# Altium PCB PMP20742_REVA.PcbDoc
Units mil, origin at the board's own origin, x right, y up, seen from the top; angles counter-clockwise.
Board outline 3000 x 1500 mil, 2 copper layers (Top Layer, Bottom Layer), stack 62 mil thick; 73 components, 37 nets, 234 pads, 52 vias.
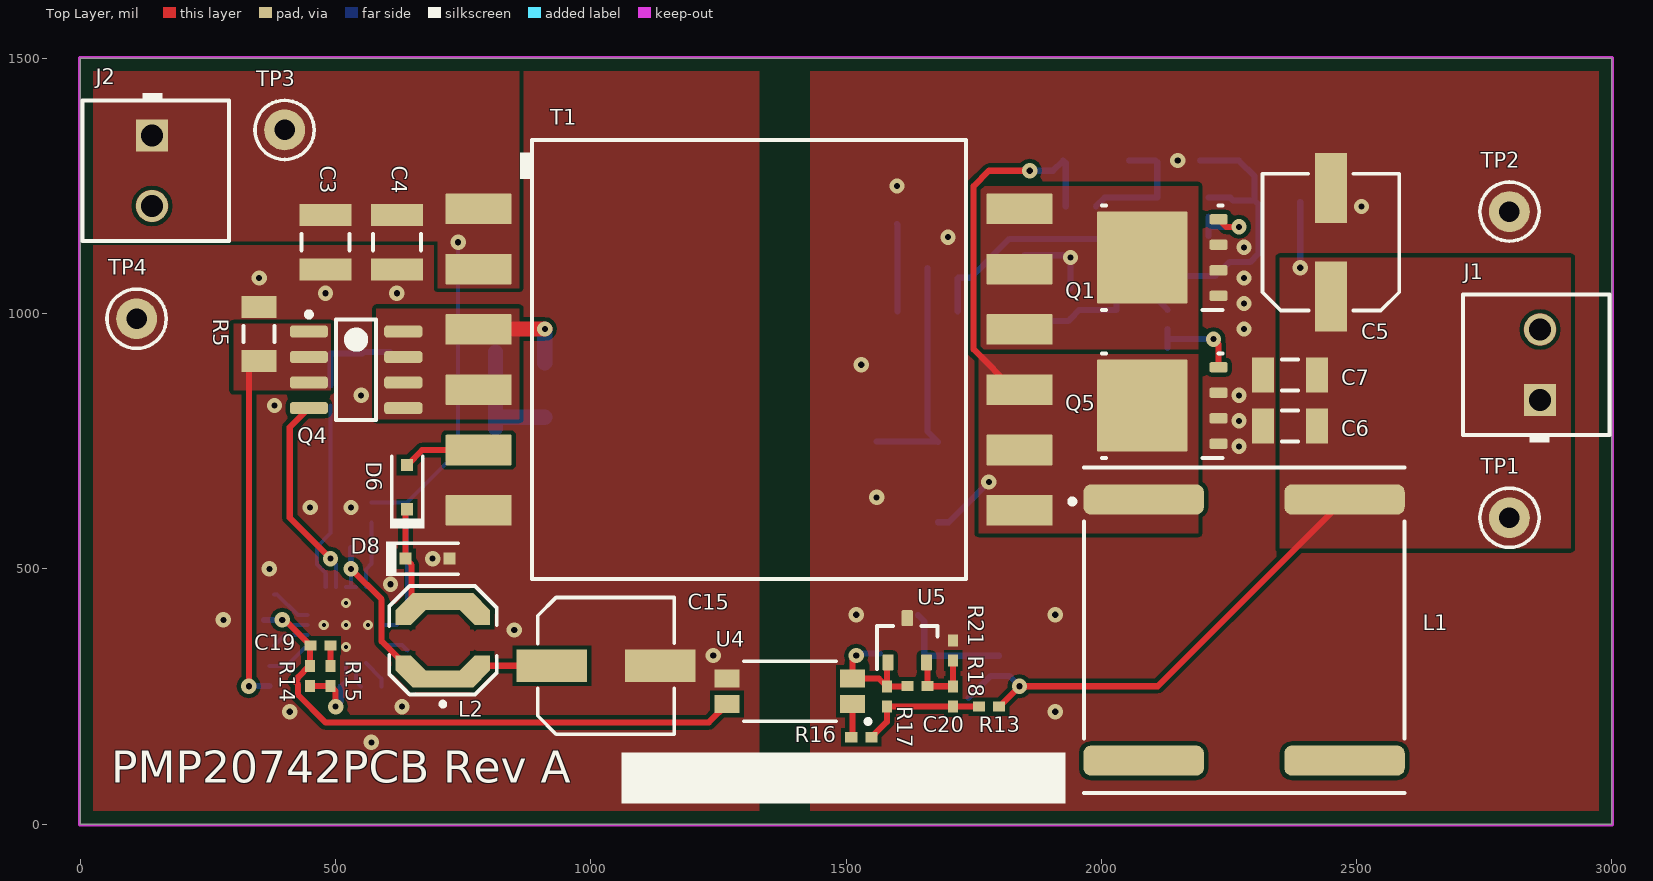
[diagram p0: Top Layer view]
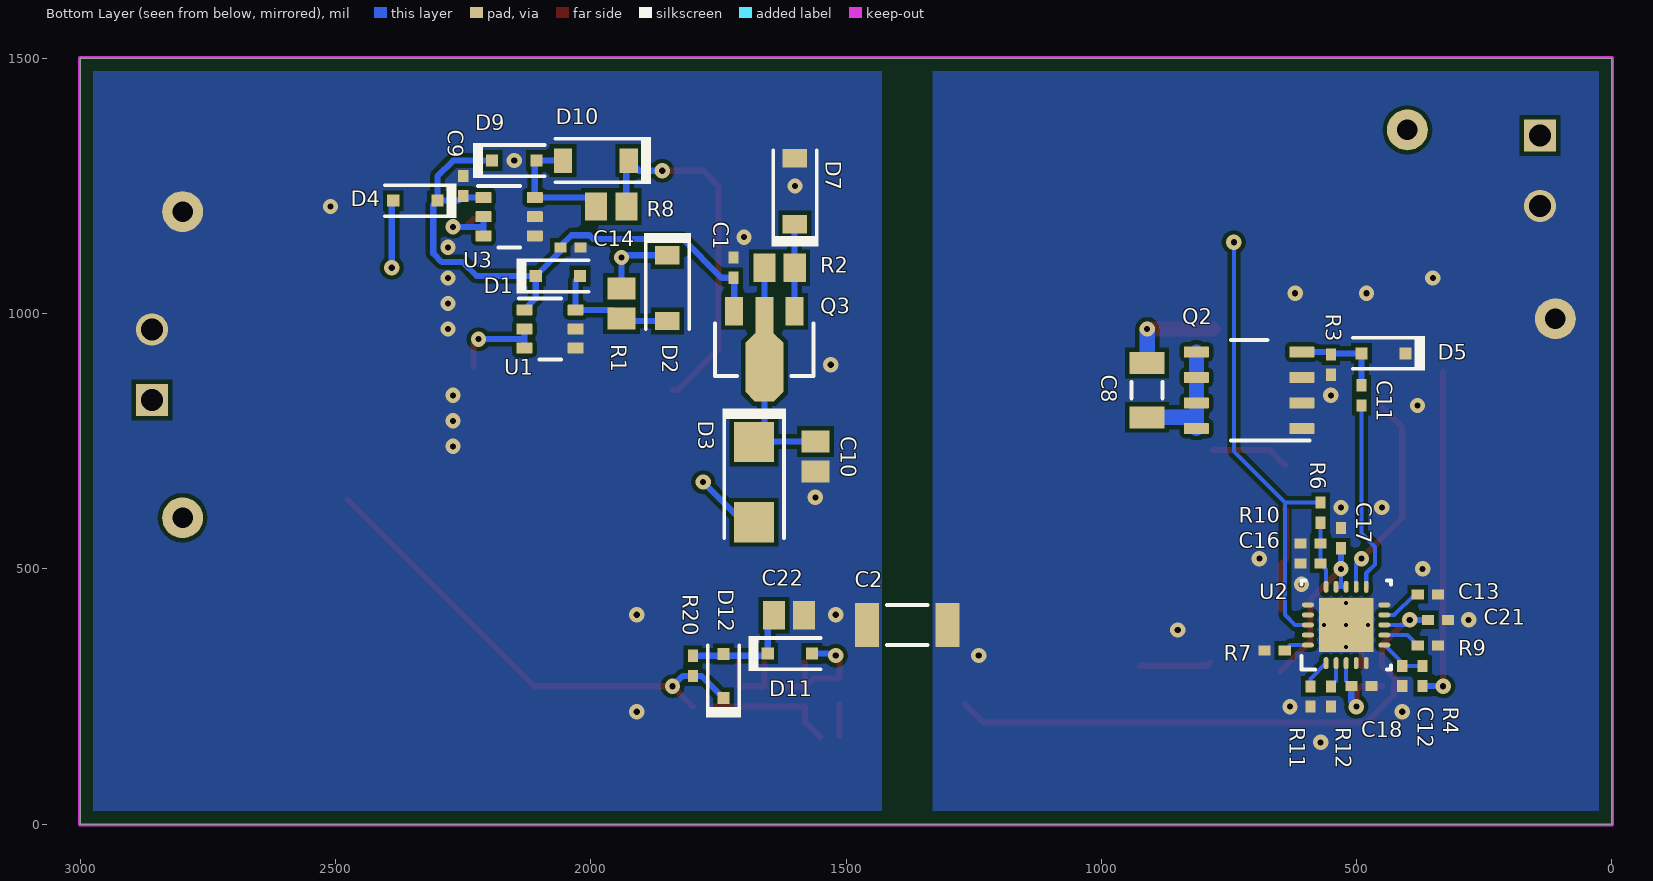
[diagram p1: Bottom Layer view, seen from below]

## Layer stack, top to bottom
Top Solder: solder mask 0.4, Solder Resist, Dk 3.5
Top Layer: signal copper 1.4
Dielectric1: core 59.2, FR-4, Dk 4.8
Bottom Layer: signal copper 1.4
Bottom Solder: solder mask 0.4, Solder Resist, Dk 3.5

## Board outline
0,0 3000,0 3000,1500 0,1500

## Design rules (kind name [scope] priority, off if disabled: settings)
AcuteAngle [All] p1: minimum=0.00000000000000E+0000 checktracksonly=FALSE
AssemblyTestPointUsage [All] p1: valid=2
BoardOutlineClearance BoardOutlineClearance_MountingHoles [OnCopper and InComponentClass('Mounting Holes')] p1: gap=25
BoardOutlineClearance BoardOutlineClearance_Poly [OnCopper and InPoly] p2: gap=25
BoardOutlineClearance [OnCopper and Not InComponentClass('Logo') and not InComponentClass('FiducialMark') and not InRegion(1000,500,4000,800)] p3: gap=25
Clearance Clearance_Keepouts [((IsTrack Or IsArc) And Not InPoly) And IsFree and IsKeepOut vs ((IsTrack Or IsArc) And Not InPoly) And IsFree and IsKeepOut] p1: gap=0
Clearance Clearance_Poly [InPolygon] p2: gap=8
Clearance [All] p3: gap=7.87
ComponentClearance ComponentClearance_MountingHoles_FiducialMarks [InComponentClass('Mounting Holes') vs InComponentClass('FiducialMark')] p1: gap=50 collisioncheckmode=3 verticalgap=10 showdistances=FALSE
ComponentClearance ComponentClearance_Shunt [InComponentClass('Header') vs InComponentClass('Shunt')] p2: gap=0 collisioncheckmode=3 verticalgap=0 showdistances=FALSE
ComponentClearance ComponentClearance_Logo [InComponentClass('Logo')] p3: gap=50 collisioncheckmode=3 verticalgap=10 showdistances=FALSE
ComponentClearance ComponentClearance_ScrewToNut [(HasFootprint('NY PMS 440 0025 PH')) vs (HasFootprint('Keystone_1902C'))] p4: gap=5 collisioncheckmode=3 verticalgap=10 showdistances=FALSE
ComponentClearance ComponentClearance_MountingHoles [InComponentClass('Mounting Holes')] p5: gap=250 collisioncheckmode=3 verticalgap=100000 showdistances=FALSE
ComponentClearance ComponentClearance_SmallPassives [HasFootprint('0201*') or HasFootprint('0402*') or HasFootprint('0508') or HasFootprint('0603*') or HasFootprint('0612') or HasFootprint('0805*') or HasFootprint('0815*') or HasFootprint('0830*') or HasFootprint('1206*') or HasFootprint('1210*') or HasFootprint('1808*') or HasFootprint('1812*') or HasFootprint('1825*') or HasFootprint('2010*') or HasFootprint('2220*') or HasFootprint('2225*') or HasFootprint('2512*') or HasFootprint('2728*') or HasFootprint('3518*') vs HasFootprint('0201*') or HasFootprint('0402*') or HasFootprint('0508') or HasFootprint('0603*') or HasFootprint('0612') or HasFootprint('0805*') or HasFootprint('0815*') or HasFootprint('0830*') or HasFootprint('1206*') or HasFootprint('1210*') or HasFootprint('1808*') or HasFootprint('1812*') or HasFootprint('1825*') or HasFootprint('2010*') or HasFootprint('2220*') or HasFootprint('2225*') or HasFootprint('2512*') or HasFootprint('2728*') or HasFootprint('3518*')] p6: gap=14.96 collisioncheckmode=3 verticalgap=10 showdistances=FALSE
ComponentClearance ComponentClearance_THtoSMT [IsThruComponent vs IsSMTComponent] p7: gap=15 collisioncheckmode=3 verticalgap=30 showdistances=FALSE
ComponentClearance ComponentClearance_THtoTH [IsThruComponent vs IsThruComponent] p8: gap=15 collisioncheckmode=3 verticalgap=30 showdistances=FALSE
ComponentClearance [All] p9: gap=15 collisioncheckmode=3 verticalgap=10 showdistances=FALSE
DiffPairsRouting [All] p1: maxlimit=100 minlimit=10 mostfreqgap=10 toplayer_minwidth=15 toplayer_maxwidth=15 toplayer_prefwidth=15 bottomlayer_minwidth=15 bottomlayer_maxwidth=15 bottomlayer_prefwidth=15 maxuncoupledlength=1000
FabricationTestPointUsage TestPointUsage [All] p1: valid=2 allowmultiple=FALSE
FabricationTestpoint Testpoint [All] p1: side=3 testpointundercomponent=TRUE minsize=40 maxsize=100 preferedsize=60 minholesize=0 maxholesize=40 preferedholesize=32 testpointgrid=1 allowsidetop=TRUE allowsidebottom=TRUE usegrid=TRUE gridtolerance=0.01
FanoutControl Fanout_LCC [IsLCC] p1: bgadir=Out bgaviamode=Centered fanoutstyle=Auto fanoutdirection=Alternating viagrid=1 // Fanout_LCC (Default Rule)
FanoutControl Fanout_BGA [IsBGA] p2: bgadir=Out bgaviamode=Centered fanoutstyle=Auto fanoutdirection=Alternating viagrid=1 // Fanout_BGA (Default Rule)
FanoutControl Fanout_Default [All] p4: bgadir=Out bgaviamode=Centered fanoutstyle=Auto fanoutdirection=Alternating viagrid=1 // Fanout_Default (Default Rule)
FanoutControl Fanout_Small [(CompPinCount < 5)] p5: bgadir=Out bgaviamode=Centered fanoutstyle=Auto fanoutdirection=OutThenIn viagrid=1 // Fanout_Small (Default Rule)
HoleSize [All] p1: absolutevalues=TRUE maxlimit=251 minlimit=7.87 maxpercent=80.000 minpercent=20.000
MinimumAnnularRing MinimumAnnularRing_ThermalPadVias [IsVia and InAnyComponent] p1: minimumring=5.91
MinimumAnnularRing [All] p2: minimumring=8
MinimumSolderMaskSliver MinimumSolderMaskSliver_Logo [InComponentClass('Logo') vs InComponentClass('Logo')] p1: minsoldermaskwidth=0.7
MinimumSolderMaskSliver [All] p2: minsoldermaskwidth=3.94
PlaneConnect [All] p1: planeconnectstyle=Direct reliefexpansion=10 reliefentries=4 reliefconductorwidth=10 reliefairgap=10
PolygonConnect [All] p1: connectstyle=Direct reliefconductorwidth=10 reliefentries=4 polygonreliefangle="90 Angle" airgapwidth=10
RoutingVias ThermalPadVias [IsVia and InAnyComponent] p1: holewidth=7.87 width=19.68 viastyle="Through Hole" minholewidth=7.87 minwidth=19.68 maxholewidth=12.99 maxwidth=23.62
RoutingVias [All] p2: holewidth=16 width=34 viastyle="Through Hole" minholewidth=7.87 minwidth=26 maxholewidth=40 maxwidth=65
SilkToBoardRegionClearance [Not ((IsComment or IsDesignator) And (Hide <> 'False')) and not InRegion(1000,500,4000,800)] p1:
SilkToSilkClearance SilkToSilkClearance_Pb-FreeLogo [(HasFootprint('Pb-Free_Overlay_Medium') OR HasFootprint('Pb-Free_Overlay_Small')) vs (HasFootprint('Pb-Free_Overlay_Medium') OR HasFootprint('Pb-Free_Overlay_Small'))] p1: silktosilkclearance=0
SilkToSilkClearance [All] p2: silktosilkclearance=4
SilkToSolderMaskClearance SilkToComponentPadClearance [IsPad and InAnycomponent] p1: minsilkscreentomaskgap=1 clearancetoexposedcopper=TRUE
SilkToSolderMaskClearance "Silk to Solder Mask Opening" [All] p2: minsilkscreentomaskgap=0.1 clearancetoexposedcopper=FALSE
SolderMaskExpansion [All] p1: expansion=1.97
Width [All] p1: maxlimit=100 minlimit=6 preferedwidth=10 checkconnectedcopper=TRUE
15 further rules are at their usual default settings.

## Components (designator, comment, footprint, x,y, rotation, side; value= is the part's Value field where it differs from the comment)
C1 "GRM155R71E104KE14D" 0402L 1720,1090 r90 bottom
C2 "STD" 1808_L 1380,390 r180 bottom
C3 "GRM32ER72A225KA35L" 1210_270L 480,1140 r270 top
C4 "GRM32ER72A225KA35L" 1210_270L 620,1140 r270 top
C5 "EEHZA1E101XP" SM_RADIAL_6.3BMM 2450,1140 r90 top
C6 "GRM31CC81E226ME11L" 1206_190L 2370,780 r180 top
C7 "GRM31CC81E226ME11L" 1206_190L 2370,880 r180 top
C8 "GRM31CR72E473KW03L" 1206_180L 910,850 r90 bottom
C9 "GRM155R71E104KE14D" 0402L 2250,1250 r90 bottom
C10 "GRM21BR72A473KA01L" 0805L 1560,720 r270 bottom
C11 "GRM155R71E104KE14D" 0402L 490,840 r90 bottom
C12 "GRM1555C1H221JA01D" 0402L 410,290 r90 bottom
C13 "GRM155R61A224KE19D" 0402L 360,450 r0 bottom
C14 "GRM155R71E104KE14D" 0402L 2040,1130 r180 bottom
C15 "EEHZA1E101XP" SM_RADIAL_6.3BMM 1030,310 r0 top
C16 "GRM155R71E473KA88D" 0402L 590,510 r180 bottom
C17 "GRM155R71E104KE14D" 0402L 530,560 r90 bottom
C18 "GRM155R61A105KE15D" 0402L 490,270 r180 bottom
C19 "GRM155R71E104KE14D" 0402L 470,350 r180 top
C20 "GRM155R71E103KA01D" 0402L 1640,270 r180 top
C21 "GRM155R61H102KA01D" 0402L 340,400 r180 bottom
C22 "GRM21BR71E475KA73L" 0805L 1611.75,409 r180 bottom
D1 "BAS316,115" sod-323 2064.57,1073.78 r180 bottom
D2 "BAV21W-7-F" SOD-123 1850,1050 r270 bottom
D3 "US1B-13-F" SMA 1680,670 r270 bottom
D4 "BAS316,115" sod-323 2343.82,1221.48 r0 bottom
D5 "BAS316,115" sod-323 446.57,922.28 r0 bottom
D6 "BAS316,115" sod-323 640,660 r90 top
D7 "MMSZ4692T1G" SOD-123 1600,1240 r90 bottom
D8 "BAS316,115" sod-323 680,520 r0 top
D9 "BAS316,115" sod-323 2150,1300 r180 bottom
D10 "BAV21W-7-F" SOD-123 1990,1300 r0 bottom
D11 "BAS316,115" sod-323 1610,334 r180 bottom
D12 "BAS316,115" sod-323 1740,290 r90 bottom
J1 "39357-0002" Molex_39357-0002 2860,900 r90 top
J2 "39357-0002" Molex_39357-0002 140,1280 r270 top
L1 "PD0120.113NL" PD0120NL 2280,380 r0 top
L2 "LPS4414-105MLB" LPS4414 710,360 r90 top
Q1 "CSD18537NQ5A" DQJ0008A 2120,1110 r180 top
Q2 "IRF6216TRPBF" SOIC-8L 710,850 r0 bottom
Q3 "BCX5616TA" SOT-89-3 1660,930 r270 bottom
Q4 "IRF7815TRPBF" SO-8L 540,890 r0 top
Q5 "CSD18537NQ5A" DQJ0008A 2120,820 r180 top
R1 "CRCW08055K10JNEA" 0805L 1940,1020 r270 bottom
R2 "CRCW080520K0FKEA" 0805L 1630,1090 r0 bottom
R3 "CRCW040210K0FKED" 0402L 550,900 r90 bottom
R4 "CRCW04021K00FKED" 0402L 370,290 r90 bottom
R5 "ERJ-8CWFR033V" 1206L 350,960 r270 top
R6 "CRCW040275K0FKED" 0402L 570,610 r90 bottom
R7 "CRCW040210K0FKED" 0402L 660,340 r180 bottom
R8 "CRCW08055K10JNEA" 0805L 1960,1210 r0 bottom
R9 "CRCW040249K9FKED" 0402L 360,350 r0 bottom
R10 "CRCW04022K80FKED" 0402L 590,550 r180 bottom
R11 "CRCW040280K6FKED" 0402L 590,250 r90 bottom
R12 "CRCW040263K4FKED" 0402L 550,250 r90 bottom
R13 "CRCW04020000Z0ED" 0402L 1780,230 r0 top
R14 "CRCW04021K00FKED" 0402L 450,290 r90 top
R15 "CRCW04021K00FKED" 0402L 490,290 r90 top
R16 "CRCW04022K00FKED" 0402L 1530,170 r0 top
R17 "CRCW04024K99FKED" 0402L 1580,250 r270 top
R18 "CRCW040210K0FKED" 0402L 1710,250 r270 top
R20 "CRCW040210K0FKED" 0402L 1800,310 r270 bottom
R21 "CRCW04022K61FKED" 0402L 1710,340 r270 top
T1 "PA2398NL" Pulse_PA2398NL 1310,910 r0 top
TP1 "5000" Keystone5000 2800,600 r0 top
TP2 "5001" Keystone5001 2800,1200 r0 top
TP3 "5000" Keystone5000 400,1360 r0 top
TP4 "5001" Keystone5001 110,990 r0 top
U1 "UCC27511DBVR" DBV0006A_L 2080,970 r180 bottom
U2 "UCC2897ARGPR" RGP0020D 520,390 r90 bottom
U3 "UCC27511DBVR" DBV0006A_L 2160,1190 r180 bottom
U4 "VOS617A-7X001T" SSOP-4_VISHAY 1390,260 r180 top
U5 "TL431AIDBZR" DBZ0003A_L 1620,360 r90 top

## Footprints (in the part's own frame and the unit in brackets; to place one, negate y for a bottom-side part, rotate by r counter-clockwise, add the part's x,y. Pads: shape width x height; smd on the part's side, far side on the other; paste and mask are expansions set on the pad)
0402L [mm] "0402 from SM-752 data"
  rect 0.6x0.5 smd: 1(-0.5,0) 2(0.5,0)
  body extent -0.55,-0.3 0.55,0.3, height 0.6
0805L [mm] "0805 from SM-752 data"
  rect 1.1x1.4 smd: 1(-0.75,0) 2(0.75,0)
  body extent -1.1,-0.72 1.1,0.72, height 1.45
1206_180L [mm] "1206_180"
  rect 1.1x1.75 smd: 1(-1.35,0) 2(1.35,0)
  silkscreen extent -0.4,-0.77 0.4,0.77, body extent -1.75,-0.95 1.75,0.95, height 1.8
1206_190L [mm] "1206_190"
  rect 1.1x1.75 smd: 1(-1.35,0) 2(1.35,0)
  silkscreen extent -0.4,-0.77 0.4,0.77, body extent -1.75,-0.95 1.75,0.95, height 1.9
1206L [mm] "1206 from SM-752 data"
  rect 1.1x1.75 smd: 1(-1.35,0) 2(1.35,0)
  silkscreen extent -0.4,-0.77 0.4,0.77, body extent -1.7,-0.9 1.7,0.9, height 1.35
1210_270L [mm] "1210"
  rect 1.1x2.6 smd: 1(-1.35,0) 2(1.35,0)
  silkscreen extent -0.4,-1.2 0.4,1.2, body extent -1.7,-1.35 1.7,1.35, height 2.7
1808_L [mm] "Chip Capacitor, Body 4.6x2.0mm, IPC High Density"
  rect 1.2x2.2 smd: 1(-2,0) 2(2,0)
  silkscreen extent -1,-1 1,1, body extent -2.47,-1.2 2.47,1.2, height 2.03
DBV0006A_L [mm] "SOT23, 6-Leads, Body 2.9x1.6mm, Pitch 0.95mm, Lead Span 2.8mm, IPC High Density"
  rrect18% 0.8x0.55 smd: 1(-1.275,0.95) 2(-1.275,0) 3(-1.275,-0.95) 4(1.275,-0.95) 5(1.275,0) 6(1.275,0.95)
  silkscreen extent -1.55,-1.53 0.55,1.53, body extent -1.42,-1.46 1.42,1.46, height 1.12
DBZ0003A_L [mm] "SOT23, 3-Leads, Body 2.9x1.3mm, Pitch 0.95mm, Lead Span 2.4mm, IPC High Density"
  rrect18% 0.8x0.55 smd: 1(-1.1,0.95) 2(-1.1,-0.95) 3(1.1,0)
  silkscreen extent -1.43,-1.5 0.7,1.5, body extent -1.26,-1.46 1.26,1.46, height 0.98
DQJ0008A [mm] "SMD, 8-Leads, Body 5.75x4.9mm"
  rrect39% 0.91x0.51 smd paste-0.05 mask-0.05: 1(-2.795,1.905) 2(-2.795,0.635) 3(-2.795,-0.635) 4(-2.795,-1.905) 5(2.795,-1.905) 6(2.795,-0.635) 7(2.795,0.635) 8(2.795,1.905)
  rrect8% 1.58x1.25 on Top Paste: 9(-0.38,1.45) 9(-0.38,0) 9(-0.38,-1.45) 9(1.4,1.45) 9(1.4,0) 9(1.4,-1.45)
  rrect3% 3.48x4.47 on Top Solder: 9(0.55,0)
  rrect2% 4.49x4.57 smd paste-2.5 mask-2.5: 9(1.005,0)
  silkscreen extent -3,-2.6 3,2.6, body extent -3.13,-2.45 3.13,2.45, height 1.15
Keystone5000 [mil] "For Keystone 500x miniature loop terminals"
  round 80 hole 40: 1(0,0)
  silkscreen extent -58,-58 58,58, body extent -49,-49 49,49, height 182
Keystone5001 [mil] "For Keystone 500x miniature loop terminals"
  round 80 hole 40: 1(0,0)
  silkscreen extent -58,-58 58,58, body extent -49,-49 49,49, height 182
LPS4414 [mm] "Coilcraft recommended land pattern Document 548-2 10/1/10"
  rect 0.85x3 smd: 1(-1.925,0) 2(1.925,0)
  rect 1.202x1.07 smd rot 45: 1(-1.55,1.55) 2(1.55,-1.55)
  rect 1.202x1.07 smd rot 135: 1(-1.55,-1.55) 2(1.55,1.55)
  rect 0.75x0.775 smd: 1(-1.125,1.963) 1(-1.125,-1.963) 2(1.125,1.963) 2(1.125,-1.963)
  silkscreen extent -3.26,-2.68 2.7,2.68, body extent -2.2,-2.2 2.2,2.2, height 1.42
Molex_39357-0002 [mm] "Terminal Block, 3.5 mm, 2x1, TH"
  rect 1.6x1.6 hole 1.1: 1(-1.75,0)
  round 1.6 hole 1.1: 2(1.75,0)
  silkscreen extent -3.86,-3.45 3.5,3.84, body extent -3.55,-3.45 3.56,3.84, height 8.51
PD0120NL [mm] "SMD, 4-Leads, Body 16.2x15.95mm"
  rrect50% 6x1.5 smd: 1(-5,6.5) 2(5,6.5) 3(5,-6.5) 4(-5,-6.5)
  silkscreen extent -8.67,-8.1 7.98,8.1, body extent -7.98,-8.1 8.01,8.1, height 8.2
Pulse_PA2398NL [mm] "SMT, 12-Leads, Body 21.84x21.6mm, Pitch 3mm"
  rrect7% 3.305x1.52 smd: 1(-13.463,7.5) 2(-13.463,4.5) 3(-13.463,1.5) 4(-13.463,-1.5) 5(-13.463,-4.5) 6(-13.463,-7.5) 7(13.463,-7.5) 8(13.463,-4.5) 9(13.463,-1.5) 10(13.463,1.5) 11(13.463,4.5) 12(13.463,7.5)
  silkscreen extent -11.4,-10.92 10.8,10.92, body extent -14.6,-10.92 14.6,10.92, height 11.44
RGP0020D [mm] "QFN, 20-Leads, Body 4x4mm, Pitch 0.5mm, Thermal Pad 2.7x2.7mm, TI Recommended"
  oval 0.6x0.24 smd: 1(-1.9,1) 2(-1.9,0.5) 3(-1.9,0) 4(-1.9,-0.5) 5(-1.9,-1) 11(1.9,-1) 12(1.9,-0.5) 13(1.9,0) 14(1.9,0.5) 15(1.9,1)
  oval 0.24x0.6 smd: 6(-1,-1.9) 7(-0.5,-1.9) 8(0,-1.9) 9(0.5,-1.9) 10(1,-1.9) 16(1,1.9) 17(0.5,1.9) 18(0,1.9) 19(-0.5,1.9) 20(-1,1.9)
  rect 2.7x2.7 smd paste-1.35: 21(0,0)
  silkscreen extent -2.22,-2.22 2.22,2.22, body extent -2.07,-2.07 2.07,2.07, height 1.01
SM_RADIAL_6.3BMM [mm] "Nichicon 6.3x7.7"
  rect 3.5x1.6 smd: 1(-2.7,0) 2(2.7,0)
  silkscreen extent -3.4,-3.4 3.4,3.4, body extent -3.4,-3.4 3.4,3.4, height 8
SMA [mm] "Molded Diode, 2-Leads, Body 4.3x2.6mm, IPC Medium Density, based on OnSemi component dimensions and land pattern"
  rect 2x2 smd: 1(-2,0) 2(2,0)
  silkscreen extent -3.66,-1.57 2.79,1.57, body extent -2.6,-1.3 2.6,1.3, height 2.42
SO-8L [mm] "SOIC, 8-Leads, Body 5.0x4.0mm (max), Pitch 1.27mm, IPC Most Density"
  rrect50% 1.9x0.6 smd: 1(-2.35,1.905) 2(-2.35,0.635) 3(-2.35,-0.635) 4(-2.35,-1.905) 5(2.35,-1.905) 6(2.35,-0.635) 7(2.35,0.635) 8(2.35,1.905)
  silkscreen extent -2.47,-2.5 1,2.88, body extent -3,-2.45 3,2.45, height 1.59
SOD-123 [mm] "On Semi recommended land pattern"
  rect 0.915x1.22 smd: 1(-1.637,0) 2(1.637,0)
  silkscreen extent -2.74,-1.17 2.03,1.17, body extent -1.93,-0.9 1.93,0.9, height 1.35
sod-323 [mm] "NXP recommended land pattern"
  rect 0.6x0.6 smd paste-0.05: 1(-1.1,0) 2(1.1,0)
  silkscreen extent -2.06,-0.86 1.53,0.86, body extent -1.3,-0.67 1.3,0.68, height 1.1
SOIC-8L [mm] "Duplicate of SO-8.  SOIC, 8-Leads, Body 5.0x4.0mm (max), Pitch 1.27mm, IPC Most Density"
  rrect18% 1.25x0.55 smd: 1(-2.625,1.905) 2(-2.625,0.635) 3(-2.625,-0.635) 4(-2.625,-1.905) 5(2.625,-1.905) 6(2.625,-0.635) 7(2.625,0.635) 8(2.625,1.905)
  silkscreen extent -3,-2.5 0.9,2.5, body extent -3,-2.45 3,2.45, height 1.63
SOT-89-3 [mm] "SOT, 3-Leads, Body 4.6 x 2.6 mm, Pitch 1.5mm"
  rect 1.4x0.9 smd: 1(-1.9,1.5) 3(-1.9,-1.5)
  rect 1.8x0.9 smd: 2(-1.7,0)
  oct 3.4x1.9 smd: 4(0.9,0)
  silkscreen extent -1.3,-2.45 1.33,2.45, body extent -2.42,-2.28 1.83,2.32, height 1.62
SSOP-4_VISHAY [mm] "Vishay Recommened"
  rect 1.25x0.9 smd: 1(-3.125,0.635) 2(-3.125,-0.635) 3(3.125,-0.635) 4(3.125,0.635)
  silkscreen extent -3.98,-1.5 2.3,1.59, body extent -3.5,-1.45 3.5,1.45, height 2.42

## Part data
C1 C9 C11 C14 C17 C19: "CAP, CERM, 0.1 µF, 25 V, +/- 10%, X7R, 0402"
C2: library part VJ1808Y102KXEAT5Z, "CAP, CERM, 1000pF, 3kV, 1808"
C3 C4: "CAP, CERM, 2.2 µF, 100 V, +/- 10%, X7R, 1210"
C5 C15: "CAP, Polymer Hybrid, 100 µF, 25 V, +/- 20%, 30 ohm, 6.3x7.7 SMD"
C6 C7: "CAP, CERM, 22 µF, 25 V, +/- 20%, X6S, 1206_190"
C8: "CAP, CERM, 0.047 µF, 250 V, +/- 10%, X7R, 1206"
C10: "CAP, CERM, 0.047 µF, 100 V, +/- 10%, X7R, 0805"
C12: "CAP, CERM, 220 pF, 50 V, +/- 5%, C0G/NP0, 0402"
C13: "CAP, CERM, 0.22uF, 10V, +/-10%, X5R, 0402"
C16: "CAP, CERM, 0.047uF, 25V, +/-10%, X7R, 0402"
C18: "CAP, CERM, 1uF, 10V, +/-10%, X5R, 0402"
C20: "CAP, CERM, 0.01 µF, 25 V, +/- 10%, X7R, 0402"
C21: "CAP, CERM, 1000 pF, 50 V, +/- 10%, X5R, 0402"
C22: "CAP, CERM, 4.7 µF, 25 V, +/- 10%, X7R, 0805"
D1 D4 D5 D6 D8 D9 D11 D12: "Diode, Ultrafast, 100V, 0.25A, SOD-323"
D2 D10: "Diode, Switching, 200V, 0.2A, SOD-123"
D3: "Diode, Ultrafast, 100V, 1A, SMA"
D7: "Diode, Zener, 6.8 V, 500 mW, SOD-123"
J1 J2: "Terminal Block, 3.5 mm, 2x1, Tin, TH"
L1: "Inductor, Wirewound, 7.6 A, 0.016 ohm, SMD"
L2: "Inductor, Shielded Drum Core, Ferrite, 1mH, 0.11A, 16.3 ohm, SMD"
Q1 Q5: "MOSFET, N-CH, 60 V, 50 A, DQJ0008A (VSONP-8)"
Q2: "MOSFET, P-CH, -150 V, -2.2 A, SOIC-8"
Q3: library part "BCX5616TA, Diodes Inc.", "Transistor, NPN, 80V, 1A, SOT-89"
Q4: "MOSFET, N-CH, 150 V, 5.1 A, SO-8"
R1 R8: "RES, 5.1k ohm, 5%, 0.125W, 0805"
R2: "RES, 20.0k ohm, 1%, 0.125W, 0805"
R3 R7 R18 R20: "RES, 10.0k ohm, 1%, 0.063W, 0402"
R4 R14 R15: "RES, 1.00k ohm, 1%, 0.063W, 0402"
R5: "RES, 0.033, 1%, 1 W, AEC-Q200 Grade 0, 1206"
R6: "RES, 75.0 k, 1%, 0.063 W, 0402"
R9: "RES, 49.9 k, 1%, 0.063 W, 0402"
R10: "RES, 2.80 k, 1%, 0.063 W, 0402"
R11: "RES, 80.6 k, 1%, 0.063 W, 0402"
R12: "RES, 63.4 k, 1%, 0.063 W, 0402"
R13: "RES, 0 ohm, 5%, 0.063W, 0402"
R16: "RES, 2.00k ohm, 1%, 0.063W, 0402"
R17: "RES, 4.99k ohm, 1%, 0.063W, 0402"
R21: "RES, 2.61k ohm, 1%, 0.063W, 0402"
T1: "Transformer, 100 uH, SMT"
TP1 TP3: "Test Point, Miniature, Red, TH"
TP2 TP4: "Test Point, Miniature, Black, TH"
U1 U3: "Single-Channel High-Speed Low-Side Gate Driver (with 4-A Peak Source and 8-A Peak Sink), DBV0006A (SOT-6)"
U2: "Advanced Active Clamp PWM Controller with Current Control, -40 to +125 degC, 20-pin QFN (RGP), Green (RoHS & no Sb/Br)"
U4: "OptoCoupler, Phototransitor, 80-160%, SSOP-4"
U5: "Adjustable Precision Shunt Regulator, 34 ppm / degC, 100 mA, -40 to 85 degC, 3-pin SOT-23 (DBZ), Green (RoHS & no Sb/Br)"

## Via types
v1: diameter 30, hole 12, Top Layer to Bottom Layer, 47 vias
v2: diameter 19.68, hole 7.87, Top Layer to Bottom Layer, 5 vias

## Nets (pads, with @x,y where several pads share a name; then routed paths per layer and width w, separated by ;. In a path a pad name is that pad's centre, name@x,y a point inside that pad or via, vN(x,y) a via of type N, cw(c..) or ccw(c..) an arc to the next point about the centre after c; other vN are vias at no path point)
BIAS: C15.1 C17.1 L2.1 U2.13 U2.14 | length 484.3
  Top Layer w12: v1(530,500) 590,440 590,357.95 L2.1@648.98,298.98 ; L2.1@787.26,315.71 792.97,310 C15.1
  Bottom Layer w8: U2.13 530,464.8 ; v1(530,500) 530,464.8 ; U2.14 530,464.8
  Bottom Layer w12: v1(530,500) C17.1
GND: C1.2 C2.1 C5.2 C6.2 C7.2 C9.2 C10.2 C14.2 C22.2 D7.2 J1.2 Q1.1 Q1.2 Q1.3 Q5.1 Q5.2 Q5.3 R21.1 TP2.1 U1.4 U1.5 U3.4 U3.5 U5.3
  other v1: 1910,220 1520,410 1910,410 1560,640 2270,740 2270,790 2270,840 1530,900 2280,970 2280,1020 2280,1070 2280,1130 1700,1150 2510,1210 1600,1250 2150,1300
NetC8_1: C8.1 Q2.5 Q2.6 Q2.7 Q2.8 | length 246.7
  Bottom Layer w30: Q2.8 813.35,796.65 813.15,796.85 C8.1 ; 813.35,797.05 Q2.7 Q2.6 Q2.5
NetC8_2: C8.2 Q4.5 Q4.6 Q4.7 Q4.8 T1.3 T1.4 | length 195.9
  Top Layer w30: T1.3@780.93,970 v1(910,970)
  Bottom Layer w30: C8.2 v1(910,970)
NetC10_1: C10.1 D3.1 Q3.2 Q3.4 R2.2 | length 468.3
  Bottom Layer w12: C10.1 D3.1@1679.21,749.53 ; R2.2@1660,1089.53 Q3.2 Q3.4 1660,768.74 D3.1@1679.21,749.53 ; D3.1 D3.1@1679.21,749.53
NetC11_2: C11.2 D5.2 Q2.4 R3.2 | length 180.6
  Bottom Layer w12: C11.2 489.87,859.81 D5.2 552.6,922.28 555.31,925 Q2.4
NetC12_2: C12.2 R4.2 U2.6 | length 95.5
  Bottom Layer w8: R4.2 C12.2 410,315.43 U2.6
NetC13_2: C13.2 U2.9 | length 82.2
  Bottom Layer w8: C13.2 385.46,450 425.77,409.68 U2.9
NetC16_2: C16.2 R6.1 R10.2 U2.15 | length 130.2
  Bottom Layer w8: U2.15 559.37,499.06 C16.2 R10.2 570.31,590 R6.1
NetC18_1: C18.1 R14.1 R15.1 U2.3 | length 177.8
  Top Layer w12: R14.1 R15.1 500,260.32 v1(500,230)
  Bottom Layer w8: C18.1 520,280.32 U2.3
  Bottom Layer w12: v1(500,230) 510,240 C18.1@510,269.68
NetC19_1: C19.1 R15.2 | length 40
  Top Layer w12: R15.2 C19.1@490,349.68
NetC19_2: C19.2 C21.1 R14.2 U2.8 U4.4 | length 1156.1
  Top Layer w12: v1(395.43,400) 400.31,400 C19.2 ; C19.2@450,349.69 R14.2 448.1,309.69 426.28,287.87 426.28,285.97 420,279.69 426.28,273.4 426.28,252.76 480,199.04 1231.01,199.04 U4.4
  Bottom Layer w8: v1(395.43,400) 405.43,390 U2.8
  Bottom Layer w12: C21.1 v1(395.43,400)
NetC20_1: C20.1 R18.1 R21.2 U5.2 | length 145
  Top Layer w12: U5.2@1659.68,314.41 C20.1 R18.1@1709.68,270 ; R18.1 R21.2
NetC20_2: C20.2 D11.2 R17.1 U4.2 U5.1 | length 257.6
  Top Layer w12: v1(1520,330) 1513.03,323.03 U4.2 1564.68,285 R17.1 ; U5.1 1580,314.09 R17.1 ; C20.2@1620,269.68 R17.1
  Bottom Layer w12: v1(1520,330) 1524,334 D11.2
NetC22_1: C22.1 D11.1 D12.2 R20.1 | length 228.5
  Bottom Layer w12: C22.1 1653.31,396.97 D11.1 1657.62,329.68 R20.1
NetD1_2: D1.2 D2.2 R1.2 U1.6 | length 258.8
  Bottom Layer w12: D2.2 1935.06,985.53 R1.2 1956.93,1007.4 U1.6 2029.8,1065.24 D1.2
NetD6_1: D6.1 D8.1 L2.2 | length 202.1
  Top Layer w12: D6.1 636.69,613.39 D8.1 648.98,507.72 L2.2@648.98,421.02
NetD6_2: D6.2 T1.5 | length 152.2
  Top Layer w12: D6.2 669.53,732.83 T1.5
NetD7_1: D7.1 Q3.1 R2.1 | length 171.1
  Bottom Layer w12: D7.1 1600.94,1174.59 Q3.1
NetD9_2: D9.2 D10.2 R8.2 U3.6 | length 253.6
  Bottom Layer w12: R8.2 2006.93,1227.4 U3.6 2109.8,1296.89 D9.2 D10.2
NetQ1_4: Q1.4 U3.2 U3.3 | length 143.4
  Top Layer w12: Q1.4 2245.04,1170 v1(2270,1170)
  Bottom Layer w12: U3.3 2210.2,1170 ; U3.2 2210.2,1170 ; v1(2270,1170) 2210.2,1170
NetQ4_1: Q4.1 Q4.2 Q4.3 R4.1 R5.2 | length 656.5
  Top Layer w12: v1(330,270) R5.2@330,886.85
  Bottom Layer w12: v1@330.32,270.32 R4.1
NetQ4_4: Q4.4 U2.12 | length 403.1
  Top Layer w12: Q4.4 410,777.52 410,600 v1(490,520)
  Bottom Layer w8: v1(490,520) 500.32,509.68 U2.12
NetQ5_4: Q5.4 U1.2 U1.3 | length 185.1
  Top Layer w12: v1(2220,950) 2230.04,939.96 Q5.4
  Bottom Layer w12: U1.3 U1.2 ; 2131.5,950 v1(2220,950)
NetR7_2: R7.2 U2.20 | length 49.9
  Bottom Layer w8: U2.20 629.68,350.63 R7.2
NetR9_2: R9.2 U2.7 | length 73.9
  Bottom Layer w8: R9.2 400,370.32 U2.7
NetR11_2: R11.2 U2.1 | length 58.2
  Bottom Layer w8: U2.1 590,284.57 R11.2
NetR12_2: R12.2 U2.2 | length 49.8
  Bottom Layer w8: U2.2 539.68,280 R12.2
NetR13_1: R13.1 R16.2 R17.2 R18.2 | length 252.9
  Top Layer w12: R16.2 1580,200.31 R17.2 R18.2 R13.1@1760,230.31
NetR16_1: R16.1 U4.1 | length 62.3
  Top Layer w12: R16.1@1513.03,172.72 U4.1
P_DRV: C11.1 U2.11 | length 373.9
  Bottom Layer w8: U2.11 480.63,491.36 463.13,508.87 463.13,543.13 490,570 C11.1
PGND: C2.2 C3.2 C4.2 C12.1 C13.1 C15.2 C16.1 C17.2 C18.2 C21.2 D5.1 D8.2 J2.2 Q2.1 Q2.2 Q2.3 R3.1 R5.1 R7.1 R9.1 R10.1 R11.1 R12.1 T1.6 TP4.1 U2.5 U2.10 U2.16 U2.21 U4.3
  other v1: 570,160 410,220 630,230 1240,330 850,380 280,400 607.6,469.72 370,500 690,520 450,620 530,620 380,820 550,840 480,1040 620,1040 350,1070
  other v2: 520,346.69 476.69,390 520,390 563.31,390 520,433.31
VDRV: C1.1 C9.1 C14.1 D1.1 D4.1 D9.1 Q3.3 U1.1 U3.1 | length 1188.4
  Bottom Layer w12: Q3.3 C1.1@1719.06,1069.37 ; C1.1 1744.2,1070.32 1820.24,1146.35 1995.39,1146.35 2002.76,1153.72 2037.87,1153.72 2059.68,1131.9 C14.1 2059.68,1121.97 D1.1 ; U1.1 2107.87,1029.72 D1.1 ; D9.1 2270,1300 2300.51,1269.49 D4.1 ; U3.1 2252.91,1227.4 2258.84,1221.48 D4.1 ; D1.1 2223.78,1073.78 2251.13,1101.13 2291.96,1101.13 2308.87,1118.04 2308.87,1213.11 D4.1
VIN: C3.1 C4.1 J2.1 R6.2 T1.1 T1.2 TP3.1 U2.18 | length 894.6
  Bottom Layer w8: R6.2 639.69,629.69 ; U2.18 620,390 639.99,409.99 639.99,629.99 740,730 v1(740,1140)
VOUT: C5.1 C6.1 C7.1 D4.2 D12.1 J1.1 L1.2 R13.2 R20.2 TP1.1 | length 1100.4
  Top Layer w12: R13.2 1800,230 v1(1840,270) 2110.94,270 L1.2
  Bottom Layer w12: D12.1 1783.62,290.31 R20.2 1819.69,290.31 v1(1840,270) ; v1(2390,1090) D4.2@2390,1218.6
VSEC1: D2.1 Q1.5 Q1.6 Q1.7 Q1.8 Q1.9@2080.43,1110 R1.1 T1.10 T1.11 T1.12 | length 146
  Bottom Layer w12: D2.1 v1@1935.53,1114.47 ; R1.1 v1(1940,1110)
VSEC2: D3.2 D10.1 L1.1 Q5.5 Q5.6 Q5.7 Q5.8 Q5.9@2080.43,820 R8.1 T1.7 T1.8 T1.9 | length 863.7
  Top Layer w12: T1.9 1829.06,850.94 1750,930 1750,1250 1780,1280 v1(1860,1280)
  Bottom Layer w12: D3.2 1701.26,591.26 v1(1780,670) ; v1(1860,1280) 1905.53,1280 D10.1 1930.47,1295.06 R8.1
pads on no net: L1.3 L1.4 Q1.9@2064.88,1052.91 Q1.9@2064.88,1110 Q1.9@2064.88,1167.09 Q1.9@2098.35,1110 Q1.9@2134.96,1052.91 Q1.9@2134.96,1110 Q1.9@2134.96,1167.09 Q5.9@2064.88,762.91 Q5.9@2064.88,820 Q5.9@2064.88,877.09 Q5.9@2098.35,820 Q5.9@2134.96,762.91 Q5.9@2134.96,820 Q5.9@2134.96,877.09 U2.4 U2.17 U2.19

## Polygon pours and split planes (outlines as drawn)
VIN on Top Layer "TOP_LAYER_VIN_P000" (solid, remove dead copper, pour order 0): 700,1500 700,1050 860,1050 860,1500
VIN on Top Layer "TOP_LAYER_VIN_P002" (solid, remove dead copper, pour order 2): 0,1500 0,1142.2 860,1142.2 860,1500
NetC8_2 on Top Layer "TOP_LAYER_NETC8_2_P004" (solid, remove dead copper, pour order 4): 580,1010 580,793.35 859.78,793.35 859.78,1010
NetQ4_1 on Top Layer "TOP_LAYER_NETQ4_1_P006" (solid, remove dead copper, pour order 6): 300,980 300,850 490,850 490,980
PGND on Top Layer "TOP_LAYER_PGND_P008" (solid, remove dead copper, pour order 8): 0,1500 0,0 1330,0 1330,1500
VSEC1 on Top Layer "TOP_LAYER_VSEC1_P012" (solid, remove dead copper, pour order 12): 1760,1250 1760,930 2190,930 2190,1250
VSEC2 on Top Layer "TOP_LAYER_VSEC2_P014" (solid, remove dead copper, pour order 14): 1760,920 1760,570 2190,570 2190,920
VOUT on Top Layer "TOP_LAYER_VOUT_P016" (solid, remove dead copper, pour order 16): 2350,1110 2350,540 2920,540 2920,1110
GND on Top Layer "TOP_LAYER_GND_P018" (solid, remove dead copper, pour order 18): 1430,1500 1430,0 3000,0 3000,1500
PGND on Bottom Layer "BOTTOM_LAYER_PGND_P010" (solid, remove dead copper, pour order 10): 0,1500 0,0 1330,0 1330,1500
GND on Bottom Layer "BOTTOM_LAYER_GND_P020" (solid, remove dead copper, pour order 20): 1430,1500 1430,0 3000,0 3000,1500

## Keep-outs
Keep-Out Layer:
  lines w5: -2.5,0 ccw(c0,0) 0,-2.5 ; -2.5,0 ccw(c0,0) 0,-2.5 ; -2.5,0 -2.5,1500 ; -2.5,1500 cw(c0,1500) 0,1502.5 ; -2.5,1500 cw(c0,1500) 0,1502.5 ; 0,-2.5 3000,-2.5 ; 0,1502.5 3000,1502.5 ; 3000,-2.5 ccw(c3000,0) 3002.5,0 ; 3000,-2.5 ccw(c3000,0) 3002.5,0 ; 3000,1502.5 cw(c3000,1500) 3002.5,1500 ; 3000,1502.5 cw(c3000,1500) 3002.5,1500 ; 3002.5,0 3002.5,1500
  text ".Layer_Name" at 577,-858.49 h60

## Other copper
Top Layer:
  text ".Layer_Name" at 577,-858.49 h60
Bottom Layer:
  text ".Layer_Name" at 577,-858.49 h60

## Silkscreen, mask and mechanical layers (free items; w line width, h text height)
Top Overlay:
  region: 1930,140 1060,140 1060,40 1930,40
  text "PMP20742PCB Rev A" at 60,60 h108.27
  text ".Layer_Name" at 577,-858.49 h60
Bottom Overlay:
  text ".Layer_Name" at 577,-858.49 h60
Top Paste:
  text ".Layer_Name" at 577,-858.49 h60
Bottom Paste:
  text ".Layer_Name" at 577,-858.49 h60
Top Solder:
  text ".Layer_Name" at 577,-858.49 h60
  text ".Layer_Name" at 577,-858.49 h60
Bottom Solder:
  text ".Layer_Name" at 577,-858.49 h60
Drill Guide:
  text ".Layer_Name" at 577,-858.49 h60
M1 Board Outline:
  the board outline again, w10
  text ".Layer_Name" at 577,-858.49 h60
M2 Board Dimensions:
  rectangle: 0,-275 125,-150
  rectangle: 125,-400 500,-275
  lines w7: 0,-275 1000,-275 ; 125,-400 125,-150 ; 250,-400 250,-150 ; 500,-400 500,-150 ; 750,-400 750,-150 ; 0,-400 1000,-400 1000,-150 0,-150 0,-400
  text ".Layer_Name" at 577,-858.49 h60
M3 3D STEP Top:
  text ".Layer_Name" at 577,-858.49 h60
M4 3D STEP Bottom:
  text ".Layer_Name" at 577,-858.49 h60
M5 Assembly Top:
  lines w10: -292,-930.17 6308,-930.17 ; -292,-726.83 6310,-726.83 ; -292,-523.5 -292,-1133.5 3713,-1133.5 6310,-1133.5 6310,-523.5 -291.5,-523.5 -291.5,-1133.5 1284,-1133.5 ; 2173,-1133.5 2173,-523.5 ; 3440,-726.83 3440,-523.5 ; 4280,-726.83 4280,-523.5 ; 4902,-1140 4902,-937.17
  text "COMPONENTS MARKED 'DNP' SHOULD NOT BE POPULATED." at 1153.5,-318.5 h60
  text "ASSEMBLY VARIANT:" at 1153,-434 h60
  text ".VariantName" at 2189,-434 h60
  text "PCB VIEWED FROM TOP SIDE" at -228.5,-655.67 h60
  text "BOARD #:" at 2248,-655.67 h60
  text ".PRJ_Number" at 2793.5,-655.67 h60
  text "REV:" at 3638,-655.67 h60
  text ".PCB_Rev" at 3929.5,-655.67 h60
  text "SVN REV:" at 4476,-655.67 h60
  text ".VersionControl_RevNumber" at 4982,-655.67 h60
  text "TID #:" at 2248,-859 h60
  text ".TID" at 2793.5,-859 h60
  text "PLOT NAME =" at -228.5,-1064.34 h60
  text ".plot_File_Name" at 577,-1064.34 h60
  text "GENERATED    :" at 2250,-1064.34 h60
  text ".Print_Date" at 3119.5,-1064.34 h60
  text ".Print_Time" at 3848.5,-1064.34 h60
  text "TEXAS INSTRUMENTS" at 5113,-1064.34 h60
M6 Assembly Bottom:
  lines w10: -292.5,-727.33 6309.5,-727.33 ; -290.5,-930.67 6309.5,-930.67 ; 1115.5,-1140.5 1115.5,-937.67 ; 1737.5,-727.33 1737.5,-524 ; 2577.5,-727.33 2577.5,-524 ; 3844.5,-1134 3844.5,-524 ; 4733.5,-1134 6309,-1134 6309,-524 -292.5,-524 -292.5,-1134 2304.5,-1134 6309.5,-1134 6309.5,-524
  text "COMPONENTS MARKED 'DNP' SHOULD NOT BE POPULATED." at 6102,-318 h60
  text ".VariantName" at 5058,-434 h60
  text "ASSEMBLY VARIANT:" at 6097,-434 h60
  text ".VersionControl_RevNumber" at 1035.5,-656.17 h60
  text "SVN REV:" at 1541.5,-656.17 h60
  text ".PCB_Rev" at 2088,-656.17 h60
  text "REV:" at 2379.5,-656.17 h60
  text ".PRJ_Number" at 3224,-656.17 h60
  text "BOARD #:" at 3769.5,-656.17 h60
  text "PCB VIEWED FROM BOTTOM SIDE" at 6246,-656.17 h60
  text ".TID" at 3224,-859.5 h60
  text "TID #:" at 3769.5,-859.5 h60
  text "TEXAS INSTRUMENTS" at 904.5,-1064.84 h60
  text ".Print_Time" at 2169,-1064.84 h60
  text ".Print_Date" at 2898,-1064.84 h60
  text "GENERATED    :" at 3767.5,-1064.84 h60
  text ".plot_File_Name" at 5440.5,-1064.84 h60
  text "PLOT NAME =" at 6246,-1064.84 h60
M9 Title Sheet:
  drawing of 57 lines, arcs and shapes, not listed
  text "1" at 739.84,8036.5 h70
  text "2" at 3235.5,8036.5 h70
  text "3" at 5724.84,8036.5 h70
  text "4" at 8231.51,8036.5 h70
  text "5" at 10730.5,8036.5 h70
  text "6" at 13235.5,8036.5 h70
  text "A" at -416.5,6893.5 h70
  text "A" at 14383.5,6893.5 h70
  text "B" at -416.5,4513.5 h70
  text "B" at 14383.5,4513.5 h70
  text "C" at -416.5,2138.5 h70
  text "C" at 14383.5,2138.5 h70
  text "PROJECT TITLE:" at 11343.5,277.5 h45
  text ".PRJ_Title" at 11393.5,144.17 h70
  text "DESIGNED FOR:" at 11343.5,-23.5 h45
  text ".PRJ_Customer" at 11393.5,-163.5 h70
  text "D" at -416.5,-231.5 h70
  text "D" at 14383.5,-231.5 h70
  text "FILE NAME:" at 11343.5,-323.5 h45
  text ".PCB_File_Name_No_Path" at 11393.5,-443.5 h70
  text "Texas Instruments (TI) and/or its licensors do not warrant the accuracy or completeness of this specification" at 6374,-605.34 h45
  text "ENGINEER:" at 11343.5,-613.5 h45
  text "LAYOUT BY:" at 12848.5,-613.5 h45
  text "or any information contained therein. TI and/or its licensors do not warrant that this design will meet" at 6329.01,-718 h45
  text ".PRJ_Engineer" at 11393.5,-768.49 h70
  text ".PCB_Layout" at 12899,-768.49 h70
  text "the specifications, will be suitable for your application or fit for any particular purpose, or will operate in" at 6329.01,-830.67 h45
  text ".Layer_Name" at 577,-858.49 h60
  text "ALTIUM DESIGNER VERSION:" at 12848.5,-923.5 h45
  text "an implementation. TI and/or its licensors do not warrant that the design is production worthy. You should" at 6329.01,-943.33 h45
  text "completely validate and test your design implementation to confirm the system functionality for your application." at 6374,-1056 h45
  text ".print_Scale" at 11393.5,-1056.83 h70
  text ".Application_BuildNumber" at 12899,-1056.83 h70
  text "1" at 739.84,-1263.5 h70
  text "2" at 3235.5,-1263.5 h70
  text "3" at 5724.84,-1263.5 h70
  text "4" at 8231.51,-1263.5 h70
  text "5" at 10730.5,-1263.5 h70
  text "6" at 13235.5,-1263.5 h70
M10 Fab Notes:
  drawing of 173 lines, arcs and shapes, not listed
  text "DESIGN INFORMATION" at 12378.02,6201 h60
  text "MIN. TRACK WIDTH:" at 11733.46,6021 h60
  text "8" at 12829.7,6021 h60
  text "MIL" at 12984.46,6021 h60
  text "MIN. CLEARANCE:" at 11733.46,5889 h60
  text "0.2" at 12769.7,5889 h60
  text "mm" at 12984.46,5889 h60
  text "MIN. VIA PAD SIZE:" at 11733.46,5757 h60
  text "24" at 12799.71,5757 h60
  text "MIL" at 12984.46,5757 h60
  text "0.05mm (2MIL)" at 12428.46,5615.29 h60
  text "MINIMUM ANNULAR RING" at 11404.23,5611 h60
  text "EXTERNAL" at 13136.46,5611 h60
  text "PER" at 11604.23,5493 h60
  text "IPC-D-275 CLASS 2 LEVEL C" at 11824.23,5493 h60
  text "MIL, HOLES" at 13312.46,5380.71 h60
  text "+/-" at 12920,5380 h60
  text "+/-" at 13774,5380 h60
  text "REGISTRATION TOLERANCES:" at 11404.23,5375 h60
  text "METAL" at 12604,5375 h60
  text "5" at 13180.2,5375 h60
  text "3" at 14013.2,5375 h60
  text "MIL" at 14129.46,5375 h60
  text "+/-" at 13774,5262 h60
  text "HOLE SIZE TOLERANCE (UNLESS OTHERWISE SPECIFIED):" at 11404.23,5257 h60
  text "3" at 14013.2,5257 h60
  text "MIL" at 14129.46,5257 h60
  text "MATERIAL:" at 11329.46,5047.54 h60
  text "FR-4 High Tg" at 12315.9,4907.21 h60
  text "FR-408" at 11750.46,4898.64 h60
  text "OTHER" at 13238.46,4898.64 h60
  text "X" at 12161,4895 h60
  text "62 MIL (1.6mm) +/-10%" at 12070.56,4735.92 h60
  text "THICKNESS:" at 11404.23,4731.64 h60
  text "X" at 11942.4,4731.64 h60
  text "OTHER" at 13355.46,4731.64 h60
  text "TOLERANCE:" at 11404.23,4573.64 h60
  text "X" at 12243.53,4573.64 h60
  text "ANSI IPC-6012 TYPE 3 CLASS 2" at 12430.48,4573.64 h60
  text "OTHER +/-" at 12430.46,4417.64 h60
  text "BOW & TWIST:" at 11404.23,4260.64 h60
  text "X" at 12243.53,4260.64 h60
  text "ANSI IPC-6012 TYPE 3 CLASS 2" at 12430.48,4260.64 h60
  text "OTHER +/-" at 12430.46,4102.13 h60
  text "DRILLING:" at 11329.46,3963.64 h60
  text "REFERENCE:" at 11404.23,3846.64 h60
  text "X" at 12052.46,3846.64 h60
  text "AS SHOWN" at 12239.46,3846.64 h60
  text "X" at 12953.46,3846.64 h60
  text "NC_DRILL FILES" at 13090.46,3846.64 h60
  text "PTH COPPER THICKNESS:" at 11404.23,3688.64 h60
  text "X" at 12534.46,3688.64 h60
  text "20-30 um" at 12671.46,3688.64 h60
  text "OTHER" at 13388.46,3688.64 h60
  text "BOARD FINISH:" at 11329.46,3529.64 h60
  text "SILKSCREEN:" at 11484.68,3411.64 h60
  text "X" at 12433.46,3411.64 h60
  text "TOP" at 12559.46,3411.64 h60
  text "X" at 12943.46,3411.64 h60
  text "BOTTOM" at 13070.46,3411.64 h60
  text "SILKSCREEN COLOR:" at 11484.68,3244.64 h60
  text "X" at 12432.42,3244.64 h60
  text "WHITE" at 12559.46,3244.64 h60
  text "OTHER" at 13070.46,3244.64 h60
  text "X" at 12563.42,3085.44 h60
  text "GREEN" at 12690.46,3085.44 h60
  text "OTHER" at 13308.46,3085.44 h60
  text "SOLDER RESIST COLOR:" at 11484.68,3074.64 h60
  text "X" at 12563.42,2915.44 h60
  text "MATTE" at 12690.46,2915.44 h60
  text "SEMI-GLOSS" at 13308,2914.8 h60
  text "IMMERSION GOLD (ENIG)" at 12390.46,2726.92 h60
  text "ENEPIG" at 13728,2723.64 h60
  text "SURFACE FINISH:" at 11329.46,2722.64 h60
  text "X" at 12203.51,2722.64 h60
  text "IMM. TIN/SILVER OR EQUIV" at 11659,2565.64 h60
  text "OTHER" at 13090.46,2565.64 h60
  text "ARRAY/PANEL:" at 11329.46,2386.64 h60
  text "CUT AND TRIM PER M1 BOARD OUTLINE" at 12390.46,2382.35 h60
  text "N.C. ROUTE" at 12390.46,2230.64 h60
  text "X" at 13069.46,2230.64 h60
  text "V. SCORE" at 13256.46,2230.64 h60
  text "CERTIFICATION:" at 11329.46,2093.64 h60
  text "MATERIALS AND WORKMANSHIP FOR ALL PCBS" at 12054.46,2093.64 h60
  text "TO MEET OR EXCEED THE REQUIREMENTS OF:" at 12054.46,1995.64 h60
  text "X" at 11680.96,1859.13 h60
  text "ANSI IPC-A-600F CLASS ->" at 11819.96,1859.13 h60
  text "X" at 13459.02,1859.13 h60
  text "2" at 13577.96,1859.14 h60
  text "1" at 13262.96,1857.64 h60
  text "3" at 13931.96,1857.64 h60
  text "X" at 12495.02,1699.64 h60
  text "RoHS" at 12631.96,1699.64 h60
  text "OTHER" at 13276.36,1699.64 h60
  text "PER ORDER" at 13673.42,1699.64 h60
  text "ALL BOARDS MUST MEET OR EXCEED UL94-V0 REQUIREMENTS." at 11357,1534 h60
  text "PCB MUST BEAR THE UL94V-0 UL REGISTERED MATERIAL ID NUMBER" at 11357,1414 h60
  text "ADDITIONAL REQUIREMENTS:" at 11329.46,1240.64 h60
  text "MICROSECTION:" at 11404.23,1125.64 h60
  text "YES" at 12309.96,1125.64 h60
  text "REQUIRED" at 13171.46,969.49 h60
  text "BARE BOARD ELEC. TEST:" at 11404.23,966.64 h60
  text "NONE" at 12709.96,966.64 h60
  text "X" at 13044.46,966.64 h60
  text "PER ORDER" at 13763.46,966.64 h60
  text ".Layer_Name" at 577,-858.49 h60
M11 Gerber Information:
  lines w10: -292,-930.17 6308,-930.17 ; -292,-726.83 6310,-726.83 ; -292,-523.5 -292,-1133.5 3713,-1133.5 6310,-1133.5 6310,-523.5 -291.5,-523.5 -291.5,-1133.5 1284,-1133.5 ; 2173,-1133.5 2173,-523.5 ; 3440,-726.83 3440,-523.5 ; 4280,-726.83 4280,-523.5 ; 4902,-1140 4902,-937.17
  text "ALL ARTWORK VIEWED FROM TOP SIDE" at -228.5,-655.67 h60
  text "BOARD #:" at 2248,-655.67 h60
  text ".PRJ_Number" at 2793.5,-655.67 h60
  text "REV:" at 3638,-655.67 h60
  text ".PCB_Rev" at 3929.5,-655.67 h60
  text "SVN REV:" at 4476,-655.67 h60
  text ".VersionControl_RevNumber" at 4982,-655.67 h60
  text "LAYER NAME =" at -228.5,-858.49 h60
  text "TID #:" at 2248,-859 h60
  text ".TID" at 2793.5,-859 h60
  text "PLOT NAME =" at -228.5,-1064.34 h60
  text ".plot_File_Name" at 577,-1064.34 h60
  text "GENERATED    :" at 2250,-1064.34 h60
  text ".Print_Date" at 3119.5,-1064.34 h60
  text ".Print_Time" at 3848.5,-1064.34 h60
  text "TEXAS INSTRUMENTS" at 5113,-1064.34 h60
M12 Stackup:
  drawing of 191 lines, arcs and shapes, not listed
  text "Layer" at 9790.34,7830 h60
  text "Name" at 10200.26,7830 h60
  text "Material" at 11130,7830 h60
  text "Thickness" at 11989.77,7830 h60
  text "Constant" at 12639.6,7830 h60
  text "Board Layer Stack" at 13209.46,7830 h60
  text "1" at 9790.34,7710 h60
  text "Top Overlay" at 10200.26,7710 h60
  text "2" at 9790.34,7590 h60
  text "Top Solder" at 10200.26,7590 h60
  text "Solder Resist" at 11130,7590 h60
  text "0.40mil" at 11989.77,7590 h60
  text "3.5" at 12639.6,7590 h60
  text "3" at 9790.34,7470 h60
  text "Top Layer" at 10200.26,7470 h60
  text "Copper" at 11130,7470 h60
  text "1.40mil" at 11989.77,7470 h60
  text "4" at 9790.34,7350 h60
  text "Dielectric1" at 10200.26,7350 h60
  text "FR-4" at 11130,7350 h60
  text "59.20mil" at 11989.77,7350 h60
  text "4.8" at 12639.6,7350 h60
  text "5" at 9790.34,7230 h60
  text "Bottom Layer" at 10200.26,7230 h60
  text "Copper" at 11130,7230 h60
  text "1.40mil" at 11989.77,7230 h60
  text "6" at 9790.34,7110 h60
  text "Bottom Solder" at 10200.26,7110 h60
  text "Solder Resist" at 11130,7110 h60
  text "0.40mil" at 11989.77,7110 h60
  text "3.5" at 12639.6,7110 h60
  text "7" at 9790.34,6990 h60
  text "Bottom Overlay" at 10200.26,6990 h60
  text ".Layer_Name" at 577,-858.49 h60
M13 Component Bodies Top:
  text ".Layer_Name" at 577,-858.49 h60
M14 Component Bodies Bottom:
  text ".Layer_Name" at 577,-858.49 h60
M15 Courtyards Top:
  text ".Layer_Name" at 577,-858.49 h60
M16 Courtyards Bottom:
  text ".Layer_Name" at 577,-858.49 h60
Drill Drawing:
  lines w10: 5336.09,2879.51 5349.9,2879.51 5363.72,2865.7 5377.53,2879.51 5391.34,2879.51 5377.53,2893.32 5391.34,2907.14 5377.53,2907.14 5363.72,2920.95 5349.9,2907.14 5336.09,2907.14 5349.9,2893.32 5336.09,2879.51 ; 5336.09,3045.27 5391.34,3045.27 5363.72,2990.02 5336.09,3045.27 ; 5336.09,3128.15 5349.9,3128.15 5349.9,3114.34 5377.53,3114.34 5377.53,3128.15 5391.34,3128.15 5391.34,3155.78 5377.53,3155.78 5377.53,3169.59 5349.9,3169.59 5349.9,3155.78 5336.09,3155.78 5336.09,3128.15 ; 5336.09,3238.66 5391.34,3238.66 5391.34,3293.91 5336.09,3293.91 5336.09,3238.66
  lines w12: 5286,2828.4 8517.49,2828.4 ; 5286,3325.68 8517.49,3325.68 ; 5623.86,2704.08 5623.86,3450 ; 5955.86,2704.08 5955.86,3450 ; 6592.43,2704.08 6592.43,3450 ; 6851.57,2704.08 6851.57,3450 ; 7226.72,2704.08 7226.72,3450 ; 7951.05,2704.08 7951.05,3450 ; 5286,2704.08 8517.49,2704.08 8517.49,3450 5286,3450 5286,2704.08
  text "Symbol" at 5360.59,3362.98 h72
  text "Quantity" at 5661.16,3362.98 h72
  text "Finished Hole Size" at 5993.16,3362.98 h72
  text "Plated" at 6629.72,3362.98 h72
  text "Hole Type" at 6888.86,3362.98 h72
  text "Drill Layer Pair" at 7264.02,3362.98 h72
  text "Hole Tolerance" at 7988.35,3362.98 h72
  text "5" at 5661.16,3238.66 h60
  text "7.87mil (0.200mm)" at 5993.16,3238.66 h60
  text "PTH" at 6629.72,3238.66 h60
  text "Round" at 6888.86,3238.66 h60
  text "Top Layer - Bottom Layer" at 7264.02,3238.66 h60
  text "47" at 5661.16,3114.34 h60
  text "12.00mil (0.305mm)" at 5993.16,3114.34 h60
  text "PTH" at 6629.72,3114.34 h60
  text "Round" at 6888.86,3114.34 h60
  text "Top Layer - Bottom Layer" at 7264.02,3114.34 h60
  text "4" at 5661.16,2990.02 h60
  text "40.00mil (1.016mm)" at 5993.16,2990.02 h60
  text "PTH" at 6629.72,2990.02 h60
  text "Round" at 6888.86,2990.02 h60
  text "Top Layer - Bottom Layer" at 7264.02,2990.02 h60
  text "4" at 5661.16,2865.7 h60
  text "43.31mil (1.100mm)" at 5993.16,2865.7 h60
  text "PTH" at 6629.72,2865.7 h60
  text "Round" at 6888.86,2865.7 h60
  text "Top Layer - Bottom Layer" at 7264.02,2865.7 h60
  text "60 Total" at 5661.16,2741.38 h60
  text ".Layer_Name" at 577,-858.49 h60
M17 Embedded Cavity:
  text ".Layer_Name" at 577,-858.49 h60
M18 Embedded Assembly:
  text ".Layer_Name" at 577,-858.49 h60
M19 Embedded Keepout:
  text ".Layer_Name" at 577,-858.49 h60

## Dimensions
0,-400 to 1000,-400 on M2 Board Dimensions
0,0 to 0,1500 on M2 Board Dimensions
0,0 to 3000,0 on M2 Board Dimensions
